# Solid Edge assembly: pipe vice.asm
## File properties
Author: CADCIM
Template: Iso Assembly.asm
Last saved by: CADCIM
Revision: 6
Application: Solid Edge
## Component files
base.par
Screw.par
moveable jaw.par
handle.par
handle screw.par
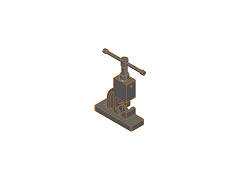
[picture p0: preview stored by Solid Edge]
